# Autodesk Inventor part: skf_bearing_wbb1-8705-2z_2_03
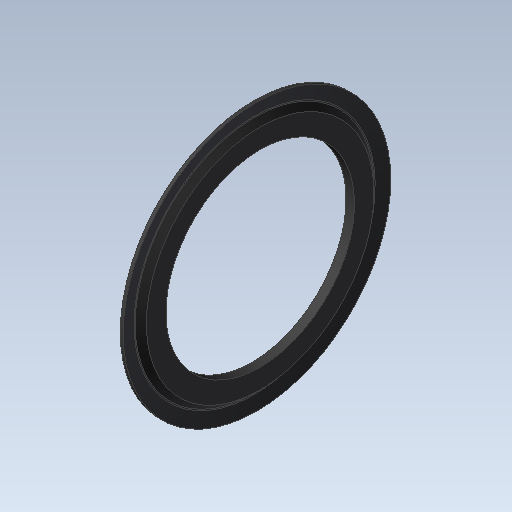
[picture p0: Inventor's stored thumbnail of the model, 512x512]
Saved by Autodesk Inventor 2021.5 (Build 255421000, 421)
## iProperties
Created: 2023-11
Part Number: skf_bearing_wbb1-8705-2z_2_03
Checked By: TraceParts S.A.
Material: Generic
Catalog Web Link: www.traceparts.com
Document SubType Name: Modeling
Designer: TraceParts
Density: 1 g/cm^3
Appearance: Default
Company: TraceParts S.A.
Author: TraceParts
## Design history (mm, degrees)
feature "skf_bearing_wbb1-8705-2z_2_03.ipt"
body "Solid1"
